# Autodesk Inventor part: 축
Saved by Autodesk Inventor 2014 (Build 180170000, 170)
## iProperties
Created: 2026-08
Part Number: 축
Material: 강철, 탄소
Document SubType Name: Modeling
Designer: dg
Density: 7.87 g/cm^3
Appearance: 반연마
Mass: 101.322 g
Surface Area: 46.7525 cm^2
Volume: 12.8744 cm^3
Author: jhkim
Creation Date: 2026-07-31
Sending System: Autodesk Inventor 2027
Preprocessor: ST-DEVELOPER v20.1
Author: dg
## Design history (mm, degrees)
node "축1"
node "솔리드1"
node "기준1"
